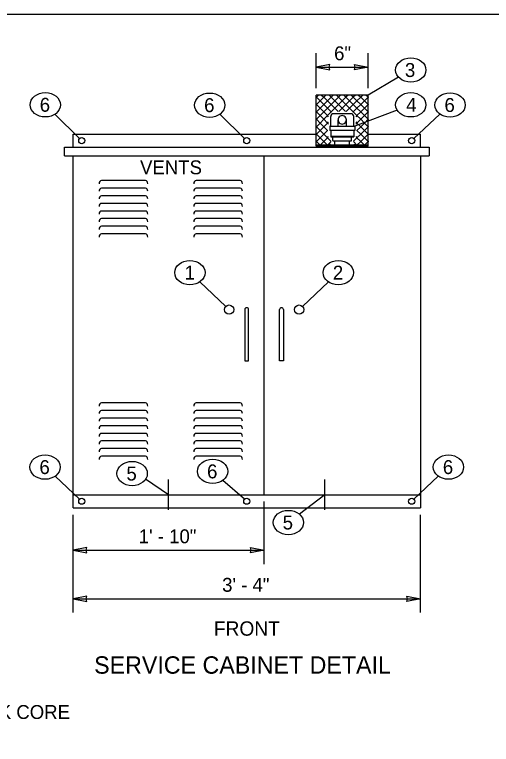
# Model space of a CAD drawing. Extents: x 99862 to 103680, y 99470 to 105076.
# Drawn here: x 100520 to 101069, y 101236 to 102076 of the extents above; entities that cross this region are included whole.
import ezdxf

# ---------------------------------------------------------------- set-up
doc = ezdxf.new("R2010")
doc.units = 0
for name, color, linetype in [('Level 1', 7, 'Continuous'), ('Level 11', 7, 'Continuous'), ('Level 15', 7, 'Continuous'), ('Level 20', 7, 'Continuous'), ('Level 40', 7, 'Continuous')]:
    doc.layers.add(name, color=color, linetype=linetype)

msp = doc.modelspace()

# ---------------------------------------------------------------- linework, layer by layer
at = {"layer": 'Level 1'}
for p, q in [((100866.96, 101925.19), (100866.96, 101982.94)), ((100926.96, 101982.94), (100866.96, 101982.94)), ((100866.96, 101980.71), (100867.18, 101980.49)), ((100867.18, 101980.49), (100866.96, 101980.27)), ((100867.18, 101980.49), (100869.64, 101982.94)), ((100871.44, 101976.24), (100867.18, 101980.49)), ((100867.18, 101971.98), (100871.44, 101976.24)), ((100875.69, 101980.49), (100871.44, 101976.24)), ((100871.44, 101976.24), (100875.69, 101971.98)), ((100873.24, 101982.94), (100875.69, 101980.49)), ((100878.14, 101982.94), (100875.69, 101980.49)), ((100875.69, 101980.49), (100879.95, 101976.24)), ((100879.95, 101976.24), (100875.69, 101971.98)), ((100879.95, 101976.24), (100884.2, 101980.49)), ((100884.2, 101971.98), (100879.95, 101976.24)), ((100884.2, 101980.49), (100881.75, 101982.94)), ((100886.65, 101982.94), (100884.2, 101980.49)), ((100884.2, 101980.49), (100888.45, 101976.24)), ((100888.45, 101976.24), (100884.2, 101971.98)), ((100888.45, 101976.24), (100892.71, 101980.49)), ((100892.71, 101971.98), (100888.45, 101976.24)), ((100892.71, 101980.49), (100890.26, 101982.94)), ((100895.16, 101982.94), (100892.71, 101980.49)), ((100892.71, 101980.49), (100896.96, 101976.24)), ((100896.96, 101976.24), (100892.71, 101971.98)), ((100896.96, 101976.24), (100901.22, 101980.49)), ((100901.22, 101971.98), (100896.96, 101976.24)), ((100901.22, 101980.49), (100898.76, 101982.94)), ((100903.67, 101982.94), (100901.22, 101980.49)), ((100901.22, 101980.49), (100905.47, 101976.24)), ((100905.47, 101976.24), (100901.22, 101971.98)), ((100905.47, 101976.24), (100909.73, 101980.49)), ((100909.73, 101971.98), (100905.47, 101976.24)), ((100909.73, 101980.49), (100907.27, 101982.94)), ((100912.18, 101982.94), (100909.73, 101980.49)), ((100909.73, 101980.49), (100913.98, 101976.24)), ((100913.98, 101976.24), (100909.73, 101971.98)), ((100913.98, 101976.24), (100918.23, 101980.49)), ((100918.23, 101971.98), (100913.98, 101976.24)), ((100915.78, 101982.94), (100918.23, 101980.49)), ((100918.23, 101980.49), (100920.69, 101982.94)), ((100918.23, 101980.49), (100922.49, 101976.24)), ((100922.49, 101976.24), (100918.23, 101971.98)), ((100922.49, 101976.24), (100926.74, 101980.49)), ((100926.74, 101971.98), (100922.49, 101976.24)), ((100926.74, 101980.49), (100924.29, 101982.94)), ((100926.96, 101980.71), (100926.74, 101980.49)), ((100926.74, 101980.49), (100926.96, 101980.27)), ((100926.96, 101925.19), (100926.96, 101982.95)), ((100866.96, 101972.21), (100867.18, 101971.98)), ((100867.18, 101971.98), (100866.96, 101971.76)), ((100871.44, 101967.73), (100867.18, 101971.98)), ((100875.69, 101971.98), (100871.44, 101967.73)), ((100875.69, 101971.98), (100879.95, 101967.73)), ((100879.95, 101967.73), (100884.2, 101971.98)), ((100884.2, 101971.98), (100888.45, 101967.73)), ((100888.45, 101967.73), (100892.71, 101971.98)), ((100892.71, 101971.98), (100896.96, 101967.73)), ((100896.96, 101967.73), (100901.22, 101971.98)), ((100901.22, 101971.98), (100905.47, 101967.73)), ((100905.47, 101967.73), (100909.73, 101971.98)), ((100909.73, 101971.98), (100913.98, 101967.73)), ((100913.98, 101967.73), (100918.23, 101971.98)), ((100918.23, 101971.98), (100922.49, 101967.73)), ((100922.49, 101967.73), (100926.74, 101971.98)), ((100926.96, 101972.2), (100926.74, 101971.98)), ((100926.74, 101971.98), (100926.96, 101971.76)), ((100866.96, 101963.7), (100867.18, 101963.48)), ((100867.18, 101963.48), (100866.96, 101963.25)), ((100867.18, 101963.48), (100871.44, 101967.73)), ((100871.44, 101959.22), (100867.18, 101963.48)), ((100871.44, 101967.73), (100875.69, 101963.48)), ((100875.69, 101963.48), (100871.44, 101959.22)), ((100879.95, 101967.73), (100875.69, 101963.48)), ((100875.69, 101963.48), (100879.95, 101959.22)), ((100884.2, 101963.48), (100879.95, 101967.73)), ((100879.95, 101959.22), (100884.2, 101963.48)), ((100888.45, 101967.73), (100884.2, 101963.48)), ((100884.2, 101963.48), (100884.42, 101963.26)), ((100906.99, 101961.45), (100886.94, 101961.45)), ((100892.33, 101963.86), (100888.45, 101967.73)), ((100896.96, 101967.73), (100893.09, 101963.86)), ((100900.84, 101963.86), (100896.96, 101967.73)), ((100905.47, 101967.73), (100901.6, 101963.86)), ((100909.73, 101963.48), (100905.47, 101967.73)), ((100909.51, 101963.26), (100909.73, 101963.48)), ((100913.98, 101967.73), (100909.73, 101963.48)), ((100909.73, 101963.48), (100913.98, 101959.22)), ((100918.23, 101963.48), (100913.98, 101967.73)), ((100913.98, 101959.22), (100918.23, 101963.48)), ((100922.49, 101967.73), (100918.23, 101963.48)), ((100918.23, 101963.48), (100922.49, 101959.22)), ((100926.74, 101963.48), (100922.49, 101967.73)), ((100922.49, 101959.22), (100926.74, 101963.48)), ((100926.96, 101963.7), (100926.74, 101963.48)), ((100926.74, 101963.48), (100926.96, 101963.26)), ((100866.96, 101955.19), (100867.18, 101954.97)), ((100867.18, 101954.97), (100866.96, 101954.75)), ((100867.18, 101954.97), (100871.44, 101959.22)), ((100871.44, 101950.71), (100867.18, 101954.97)), ((100871.44, 101959.22), (100875.69, 101954.97)), ((100875.69, 101954.97), (100871.44, 101950.71)), ((100879.95, 101959.22), (100875.69, 101954.97)), ((100875.69, 101954.97), (100879.95, 101950.71)), ((100881.32, 101957.85), (100879.95, 101959.22)), ((100879.95, 101950.71), (100881.32, 101952.09)), ((100883.73, 101947.01), (100883.73, 101958.24)), ((100892.15, 101947.01), (100892.15, 101954.39)), ((100901.78, 101947.01), (100901.78, 101954.39)), ((100910.2, 101947.01), (100910.2, 101958.24)), ((100913.98, 101959.22), (100912.6, 101957.85)), ((100912.6, 101952.09), (100913.98, 101950.71)), ((100918.23, 101954.97), (100913.98, 101959.22)), ((100913.98, 101950.71), (100918.23, 101954.97)), ((100922.49, 101959.22), (100918.23, 101954.97)), ((100918.23, 101954.97), (100922.49, 101950.71)), ((100926.74, 101954.97), (100922.49, 101959.22)), ((100922.49, 101950.71), (100926.74, 101954.97)), ((100926.96, 101955.19), (100926.74, 101954.97)), ((100926.74, 101954.97), (100926.96, 101954.75)), ((100866.96, 101946.68), (100867.18, 101946.46)), ((100867.18, 101946.46), (100866.96, 101946.24)), ((100867.18, 101946.46), (100871.44, 101950.71)), ((100871.44, 101942.2), (100867.18, 101946.46)), ((100871.44, 101950.71), (100875.69, 101946.46)), ((100875.69, 101946.46), (100871.44, 101942.2)), ((100879.95, 101950.71), (100875.69, 101946.46)), ((100875.69, 101946.46), (100879.95, 101942.2)), ((100881.24, 101949.42), (100879.95, 101950.71)), ((100883.73, 101947.01), (100882.52, 101947.01)), ((100882.52, 101947.01), (100882.52, 101942.2)), ((100883.73, 101947.01), (100910.2, 101947.01)), ((100910.2, 101947.01), (100911.4, 101947.01)), ((100911.4, 101947.01), (100911.4, 101942.2)), ((100913.98, 101950.71), (100912.68, 101949.42)), ((100918.23, 101946.46), (100913.98, 101950.71)), ((100913.98, 101942.2), (100918.23, 101946.46)), ((100922.49, 101950.71), (100918.23, 101946.46)), ((100918.23, 101946.46), (100922.49, 101942.2)), ((100926.74, 101946.46), (100922.49, 101950.71)), ((100922.49, 101942.2), (100926.74, 101946.46)), ((100926.96, 101946.68), (100926.74, 101946.46)), ((100926.74, 101946.46), (100926.96, 101946.24)), ((100866.96, 101938.17), (100867.18, 101937.95)), ((100867.18, 101937.95), (100866.96, 101937.73)), ((100867.18, 101937.95), (100871.44, 101942.2)), ((100871.44, 101933.7), (100867.18, 101937.95)), ((100871.44, 101942.2), (100875.69, 101937.95)), ((100875.69, 101937.95), (100871.44, 101933.7)), ((100879.95, 101942.2), (100875.69, 101937.95)), ((100875.69, 101937.95), (100879.95, 101933.7)), ((100879.95, 101942.2), (100880.12, 101942.38)), ((100880.12, 101942.03), (100879.95, 101942.2)), ((100879.95, 101933.7), (100881.32, 101935.07)), ((100911.4, 101942.2), (100882.52, 101942.2)), ((100883.73, 101942.2), (100883.73, 101934.98)), ((100883.73, 101935.58), (100910.2, 101935.58)), ((100883.73, 101934.98), (100910.2, 101934.98)), ((100886.13, 101930.77), (100886.13, 101934.98)), ((100907.79, 101930.77), (100907.79, 101934.98)), ((100910.2, 101942.2), (100910.2, 101934.98)), ((100912.6, 101935.07), (100913.98, 101933.7)), ((100913.81, 101942.38), (100913.98, 101942.2)), ((100913.98, 101942.2), (100913.81, 101942.03)), ((100918.23, 101937.95), (100913.98, 101942.2)), ((100913.98, 101933.7), (100918.23, 101937.95)), ((100922.49, 101942.2), (100918.23, 101937.95)), ((100918.23, 101937.95), (100922.49, 101933.7)), ((100926.74, 101937.95), (100922.49, 101942.2)), ((100922.49, 101933.7), (100926.74, 101937.95)), ((100926.96, 101938.17), (100926.74, 101937.95)), ((100926.74, 101937.95), (100926.96, 101937.73)), ((100866.96, 101929.66), (100867.18, 101929.44)), ((100867.18, 101929.44), (100866.96, 101929.22)), ((100867.18, 101929.44), (100871.44, 101933.7)), ((100871.44, 101925.19), (100867.18, 101929.44)), ((100871.44, 101933.7), (100875.69, 101929.44)), ((100875.69, 101929.44), (100871.44, 101925.19)), ((100879.95, 101933.7), (100875.69, 101929.44)), ((100875.69, 101929.44), (100879.95, 101925.19)), ((100883.91, 101929.73), (100879.95, 101933.7)), ((100879.95, 101925.19), (100884.09, 101929.33)), ((100886.73, 101930.16), (100907.19, 101930.16)), ((100888.54, 101925.35), (100888.54, 101930.16)), ((100905.39, 101925.35), (100905.39, 101930.16)), ((100909.83, 101929.33), (100913.98, 101925.19)), ((100913.98, 101933.7), (100910.01, 101929.73)), ((100918.23, 101929.44), (100913.98, 101933.7)), ((100913.98, 101925.19), (100918.23, 101929.44)), ((100922.49, 101933.7), (100918.23, 101929.44)), ((100918.23, 101929.44), (100922.49, 101925.19)), ((100926.74, 101929.44), (100922.49, 101933.7)), ((100922.49, 101925.19), (100926.74, 101929.44)), ((100926.96, 101929.66), (100926.74, 101929.44)), ((100926.74, 101929.44), (100926.96, 101929.22)), ((100926.96, 101925.19), (100866.96, 101925.19)), ((100866.96, 101924.15), (100866.96, 101925.09)), ((100926.96, 101925.09), (100866.96, 101925.09)), ((100926.96, 101924.15), (100866.96, 101924.15)), ((100890.95, 101922.94), (100902.98, 101922.94)), ((100926.96, 101924.15), (100926.96, 101925.09)), ((100784.75, 101735.95), (100784.75, 101732.99)), ((100784.75, 101732.99), (100784.75, 101676.86)), ((100789.18, 101732.99), (100789.18, 101735.95)), ((100789.18, 101676.86), (100789.18, 101732.99)), ((100824.75, 101732.99), (100824.75, 101735.95)), ((100824.75, 101676.86), (100824.75, 101732.99)), ((100829.18, 101735.95), (100829.18, 101732.99)), ((100829.18, 101732.99), (100829.18, 101676.86)), ((100784.75, 101676.86), (100789.18, 101676.86)), ((100829.18, 101676.86), (100824.75, 101676.86))]:
    msp.add_line(p, q, dxfattribs=at)
msp.add_lwpolyline([(99862, 99999.5), (103151, 99999.5), (103151, 102075.5), (99862, 102075.5)], close=True, dxfattribs=at)
for centre in [(100766.65, 101735.95), (100847.27, 101735.95)]:
    msp.add_circle(centre, 5.34, dxfattribs=at)
for centre, radius, start, end in [((100886.94, 101958.24), 3.21, 90, 180), ((100906.99, 101958.24), 3.21, 0, 90), ((100896.96, 101954.39), 4.81, 359.99971, 180), ((100896.96, 101954.39), 4.81, 180, 0.00029), ((100886.73, 101930.77), 0.602, 180, 270), ((100907.19, 101930.77), 0.602, 270, 0), ((100890.95, 101925.35), 2.41, 180, 270), ((100902.98, 101925.35), 2.41, 270, 0), ((100786.96, 101735.95), 2.22, 0, 180), ((100826.96, 101735.95), 2.22, 0, 180)]:
    msp.add_arc(centre, radius, start, end, dxfattribs=at)
at = {"layer": 'Level 11'}
for p, q in [((100670.43, 101884.5), (100619.52, 101884.5)), ((100779.46, 101884.5), (100728.55, 101884.5)), ((100670.43, 101875.73), (100619.52, 101875.73)), ((100779.46, 101875.73), (100728.55, 101875.73)), ((100670.43, 101866.97), (100619.52, 101866.97)), ((100779.46, 101866.97), (100728.55, 101866.97)), ((100670.43, 101858.21), (100619.52, 101858.21)), ((100779.46, 101858.21), (100728.55, 101858.21)), ((100670.43, 101849.44), (100619.52, 101849.44)), ((100779.46, 101849.44), (100728.55, 101849.44)), ((100670.43, 101840.68), (100619.52, 101840.68)), ((100779.46, 101840.68), (100728.55, 101840.68)), ((100670.43, 101831.92), (100619.52, 101831.92)), ((100779.46, 101831.92), (100728.55, 101831.92)), ((100670.43, 101823.15), (100619.52, 101823.15)), ((100779.46, 101823.15), (100728.55, 101823.15)), ((100670.43, 101628.62), (100619.52, 101628.62)), ((100779.46, 101628.62), (100728.55, 101628.62)), ((100670.43, 101619.85), (100619.52, 101619.85)), ((100779.46, 101619.85), (100728.55, 101619.85)), ((100670.43, 101611.09), (100619.52, 101611.09)), ((100779.46, 101611.09), (100728.55, 101611.09)), ((100670.43, 101602.33), (100619.52, 101602.33)), ((100779.46, 101602.33), (100728.55, 101602.33)), ((100670.43, 101593.56), (100619.52, 101593.56)), ((100779.46, 101593.56), (100728.55, 101593.56)), ((100670.43, 101584.8), (100619.52, 101584.8)), ((100779.46, 101584.8), (100728.55, 101584.8)), ((100670.43, 101576.04), (100619.52, 101576.04)), ((100779.46, 101576.04), (100728.55, 101576.04)), ((100670.43, 101567.27), (100619.52, 101567.27)), ((100779.46, 101567.27), (100728.55, 101567.27))]:
    msp.add_line(p, q, dxfattribs=at)
for centre, start_param, end_param in [((100619.52, 101880.86), 0, 1.570796), ((100670.43, 101880.86), 4.712389, 6.283185), ((100728.55, 101880.86), 0, 1.570796), ((100779.46, 101880.86), 4.712389, 6.283185), ((100619.52, 101872.1), 0, 1.570796), ((100670.43, 101872.1), 4.712389, 6.283185), ((100728.55, 101872.1), 0, 1.570796), ((100779.46, 101872.1), 4.712389, 6.283185), ((100619.52, 101863.33), 0, 1.570796), ((100670.43, 101863.33), 4.712389, 6.283185), ((100728.55, 101863.33), 0, 1.570796), ((100779.46, 101863.33), 4.712389, 6.283185), ((100619.52, 101854.57), 0, 1.570796), ((100670.43, 101854.57), 4.712389, 6.283185), ((100728.55, 101854.57), 0, 1.570796), ((100779.46, 101854.57), 4.712389, 6.283185), ((100619.52, 101845.81), 0, 1.570796), ((100670.43, 101845.81), 4.712389, 6.283185), ((100728.55, 101845.81), 0, 1.570796), ((100779.46, 101845.81), 4.712389, 6.283185), ((100619.52, 101837.04), 0, 1.570796), ((100670.43, 101837.04), 4.712389, 6.283185), ((100728.55, 101837.04), 0, 1.570796), ((100779.46, 101837.04), 4.712389, 6.283185), ((100619.52, 101828.28), 0, 1.570796), ((100670.43, 101828.28), 4.712389, 6.283185), ((100728.55, 101828.28), 0, 1.570796), ((100779.46, 101828.28), 4.712389, 6.283185), ((100619.52, 101819.51), 0, 1.570796), ((100670.43, 101819.51), 4.712389, 6.283185), ((100728.55, 101819.51), 0, 1.570796), ((100779.46, 101819.51), 4.712389, 6.283185), ((100619.52, 101624.98), 0, 1.570796), ((100670.43, 101624.98), 4.712389, 6.283185), ((100728.55, 101624.98), 0, 1.570796), ((100779.46, 101624.98), 4.712389, 6.283185), ((100619.52, 101616.22), 0, 1.570796), ((100670.43, 101616.22), 4.712389, 6.283185), ((100728.55, 101616.22), 0, 1.570796), ((100779.46, 101616.22), 4.712389, 6.283185), ((100619.52, 101607.45), 0, 1.570796), ((100670.43, 101607.45), 4.712389, 6.283185), ((100728.55, 101607.45), 0, 1.570796), ((100779.46, 101607.45), 4.712389, 6.283185), ((100619.52, 101598.69), 0, 1.570796), ((100670.43, 101598.69), 4.712389, 6.283185), ((100728.55, 101598.69), 0, 1.570796), ((100779.46, 101598.69), 4.712389, 6.283185), ((100619.52, 101589.93), 0, 1.570796), ((100670.43, 101589.93), 4.712389, 6.283185), ((100728.55, 101589.93), 0, 1.570796), ((100779.46, 101589.93), 4.712389, 6.283185), ((100619.52, 101581.16), 0, 1.570796), ((100670.43, 101581.16), 4.712389, 6.283185), ((100728.55, 101581.16), 0, 1.570796), ((100779.46, 101581.16), 4.712389, 6.283185), ((100619.52, 101572.4), 0, 1.570796), ((100670.43, 101572.4), 4.712389, 6.283185), ((100728.55, 101572.4), 0, 1.570796), ((100779.46, 101572.4), 4.712389, 6.283185), ((100619.52, 101563.63), 0, 1.570796), ((100670.43, 101563.63), 4.712389, 6.283185), ((100728.55, 101563.63), 0, 1.570796), ((100779.46, 101563.63), 4.712389, 6.283185)]:
    msp.add_ellipse(centre, major_axis=(0, 3.64), ratio=0.707107, start_param=start_param, end_param=end_param, dxfattribs=at)
at = {"layer": 'Level 15'}
for p, q in [((100866.96, 101990.94), (100866.96, 102030.94)), ((100926.96, 101990.94), (100926.96, 102030.94)), ((100866.96, 102014.94), (100926.96, 102014.94)), ((100961.82, 102003.41), (100926.96, 101982.94)), ((100594.47, 101932.9), (100566.01, 101960.84)), ((100784.47, 101932.9), (100756.01, 101960.84)), ((100960.14, 101965.65), (100911.4, 101947.01)), ((100979.51, 101932.84), (101009.48, 101961.03)), ((100586.96, 101922.94), (100986.96, 101922.94)), ((100586.96, 101912.94), (100986.96, 101912.94)), ((100762.8, 101739.65), (100732.83, 101767.83)), ((100851.12, 101739.65), (100881.09, 101767.83)), ((100594.41, 101517.84), (100566.3, 101544.28)), ((100696.96, 101522.94), (100670.4, 101540.68)), ((100696.96, 101505.44), (100696.96, 101540.44)), ((100876.96, 101505.44), (100876.96, 101540.44)), ((100979.51, 101517.84), (101007.62, 101544.28)), ((100784.41, 101517.84), (100759.38, 101539.35)), ((100876.96, 101522.94), (100847.63, 101500.6)), ((100806.96, 101443.08), (100806.96, 101514.94)), ((100586.96, 101387.22), (100586.96, 101499.94)), ((100986.96, 101387.22), (100986.96, 101499.94)), ((100586.96, 101459.08), (100806.96, 101459.08)), ((100586.96, 101403.22), (100986.96, 101403.22))]:
    msp.add_line(p, q, dxfattribs=at)
for points in [[(100866.96, 102014.94), (100882.69, 102011.86), (100881.96, 102014.94), (100882.69, 102018.03)], [(100926.96, 102014.94), (100911.24, 102011.86), (100911.97, 102014.94), (100911.24, 102018.03)], [(100586.96, 101459.08), (100602.69, 101456), (100601.96, 101459.08), (100602.69, 101462.17)], [(100806.96, 101459.08), (100791.24, 101456), (100791.97, 101459.08), (100791.24, 101462.17)], [(100586.96, 101403.22), (100602.69, 101400.14), (100601.96, 101403.22), (100602.69, 101406.31)], [(100986.96, 101403.22), (100971.24, 101400.14), (100971.97, 101403.22), (100971.24, 101406.31)]]:
    msp.add_lwpolyline(points, close=True, dxfattribs=at)
for centre in [(100596.96, 101930.44), (100786.96, 101930.44), (100976.96, 101930.44), (100596.96, 101515.44), (100786.96, 101515.44), (100976.96, 101515.44)]:
    msp.add_circle(centre, 3.5, dxfattribs=at)
at = {"layer": 'Level 20'}
for centre, major_axis in [((100975.93, 102011.69), (-17.5, 0)), ((100554.96, 101971.69), (-17.5, 0)), ((100744.34, 101971.26), (-17.5, 0)), ((100975.93, 101971.69), (-17.5, 0)), ((101021.16, 101971.45), (-17.5, 0)), ((100721.49, 101778.5), (-17.5, 0)), ((100892.43, 101778.5), (-17.5, 0)), ((100554.62, 101554.71), (-17.5, 0)), ((101019.3, 101554.71), (-17.5, 0)), ((100654.96, 101547.28), (-17.5, 0)), ((100747.7, 101549.78), (-17.5, 0)), ((100834.96, 101490.94), (17.5, 0))]:
    msp.add_ellipse(centre, major_axis=major_axis, ratio=0.8, dxfattribs=at)
at = {"layer": 'Level 40'}
for p, q in [((100586.96, 101937.94), (100866.96, 101937.94)), ((100586.96, 101922.94), (100586.96, 101937.94)), ((100926.96, 101937.94), (100986.96, 101937.94)), ((100986.96, 101922.94), (100986.96, 101937.94)), ((100576.96, 101922.94), (100586.96, 101922.94)), ((100576.96, 101912.94), (100576.96, 101922.94)), ((100986.96, 101922.94), (100996.96, 101922.94)), ((100996.96, 101922.94), (100996.96, 101912.94)), ((100576.96, 101912.94), (100586.96, 101912.94)), ((100586.96, 101507.94), (100586.96, 101912.94)), ((100806.96, 101522.94), (100806.96, 101912.94)), ((100986.96, 101912.94), (100986.96, 101507.94)), ((100986.96, 101912.94), (100996.96, 101912.94)), ((100586.96, 101522.94), (100986.96, 101522.94)), ((100586.96, 101507.94), (100986.96, 101507.94))]:
    msp.add_line(p, q, dxfattribs=at)
for points in [[(100883.51, 101925.11), (100883.51, 101925.88), (100881.54, 101925.88), (100881.54, 101925.11)], [(100910.42, 101925.11), (100910.42, 101925.88), (100912.39, 101925.88), (100912.39, 101925.11)], [(100883.87, 101923.19), (100883.87, 101922.94), (100881.18, 101922.94), (100881.18, 101923.19)], [(100883.84, 101923.35), (100883.84, 101923.19), (100881.21, 101923.19), (100881.21, 101923.35)], [(100883.51, 101923.35), (100883.51, 101924.15), (100881.54, 101924.15), (100881.54, 101923.35)], [(100910.06, 101923.19), (100910.06, 101922.94), (100912.74, 101922.94), (100912.74, 101923.19)], [(100910.09, 101923.35), (100910.09, 101923.19), (100912.72, 101923.19), (100912.72, 101923.35)], [(100910.42, 101923.35), (100910.42, 101924.15), (100912.39, 101924.15), (100912.39, 101923.35)]]:
    msp.add_lwpolyline(points, close=True, dxfattribs=at)

# ---------------------------------------------------------------- texts
at = {"layer": 'Level 20'}
for s, p in [('6"', (100887.6, 102022.94)), ('VENTS', (100664.08, 101891.73)), ('1\' - 10"', (100662.58, 101467.08)), ('3\' - 4"', (100758.63, 101411.22)), ('TRANSFORMER SIDE DOOR WITH BEST CX 6-PIN LOCK CORE', (99941.45, 101264.85))]:
    msp.add_text(s, height=16, rotation=360, dxfattribs=at).set_placement(p)
for s, height, p in [('3', 16, (100969.19, 102003.69)), ('6', 16, (100548.53, 101963.69)), ('6', 16, (100737.9, 101963.26)), ('4', 16, (100970.65, 101963.69)), ('6', 16, (101014.73, 101963.45)), ('1', 16, (100715.42, 101770.5)), ('2', 16, (100886.15, 101770.5)), ('6', 16, (100548.19, 101546.71)), ('6', 16, (100741.27, 101541.78)), ('6', 16, (101012.87, 101546.71)), ('5', 16, (100648.38, 101539.28)), ('5', 16, (100828.38, 101482.94)), ('FRONT', 16.5, (100749.14, 101360.69)), ('SERVICE CABINET DETAIL', 20, (100611.21, 101316.94))]:
    msp.add_text(s, height=height, dxfattribs=at).set_placement(p)

doc.saveas('drawing.dxf')
